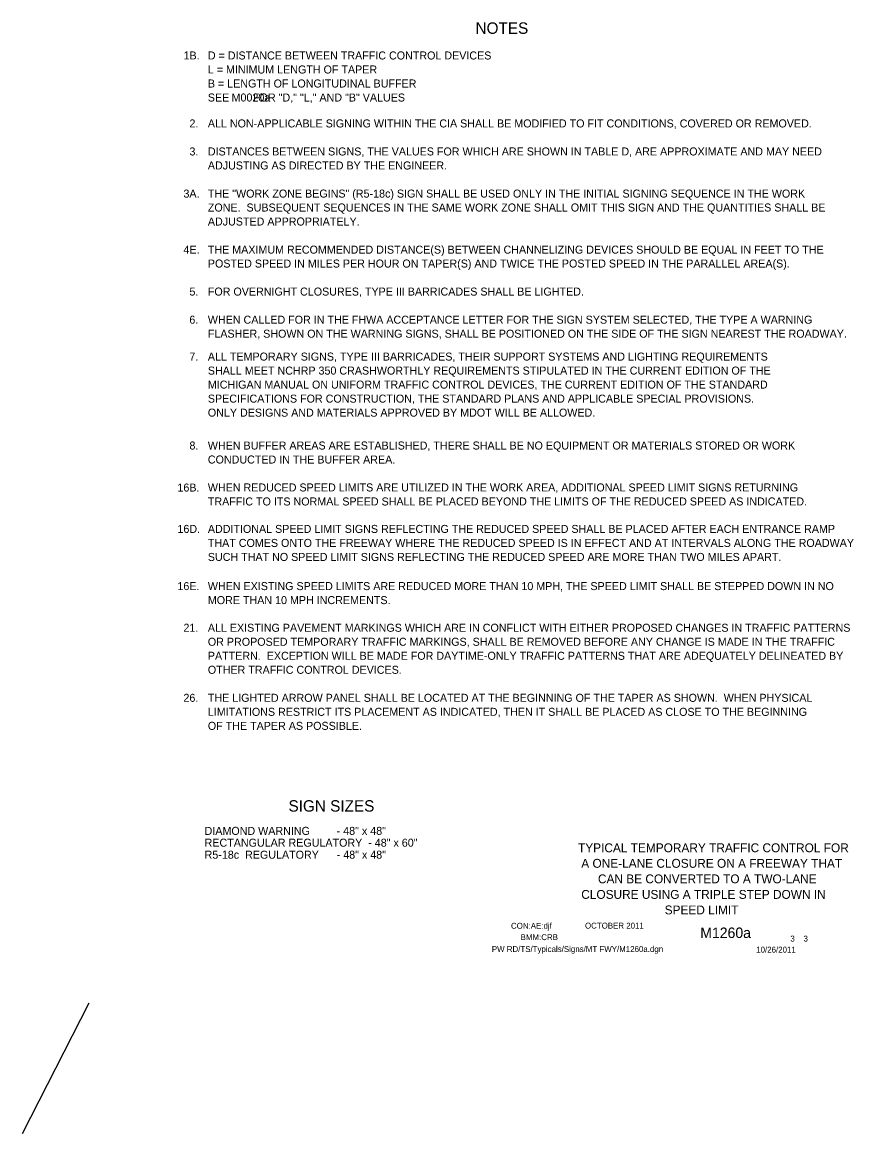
# Model space of a CAD drawing. Extents: x 16503 to 19508, y 5728 to 6974.
# Drawn here: x 18636 to 19508, y 5743 to 6909 of the extents above; entities that cross this region are included whole.
import ezdxf

# ---------------------------------------------------------------- set-up
doc = ezdxf.new("R2010")
doc.units = 0
for name, color, linetype in [('BORDER', 7, 'Continuous'), ('BORDER_SIGNAL_WO', 7, 'Continuous'), ('TYPICAL_TEXT_DIMEN_PR', 7, 'Continuous')]:
    doc.layers.add(name, color=color, linetype=linetype)

msp = doc.modelspace()

# ---------------------------------------------------------------- linework, layer by layer
at = {"layer": 'TYPICAL_TEXT_DIMEN_PR'}
msp.add_line((18705.8, 5880), (18636, 5743), dxfattribs=at)

# ---------------------------------------------------------------- texts
at = {"layer": 'BORDER'}
for s, p in [('TYPICAL TEMPORARY TRAFFIC CONTROL FOR', (19219, 6038.4)), ('A ONE-LANE CLOSURE ON A FREEWAY THAT', (19222.4, 6022.1)), ('CAN BE CONVERTED TO A TWO-LANE ', (19239.9, 6005.8)), ('CLOSURE USING A TRIPLE STEP DOWN IN ', (19222.4, 5989.5)), ('SPEED LIMIT', (19309.9, 5973.2))]:
    msp.add_text(s, height=9.3, dxfattribs=at).set_placement(p)
at = {"layer": 'BORDER_SIGNAL_WO'}
for s, height, p in [('CON:AE:djf  ', 6.2, (19148.7, 5958.1)), ('    OCTOBER 2011    ', 6.2, (19217.1, 5958.3)), ('    M1260a   ', 11, (19330.9, 5948.4)), ('BMM:CRB   ', 6.2, (19158.8, 5946.2)), (' 3    3 ', 6.2, (19439.4, 5944.7)), ('PW RD/TS/Typicals/Signs/MT FWY/M1260a.dgn      ', 6.2, (19128.6, 5933.7)), ('10/26/2011    ', 6.2, (19405.9, 5933.1))]:
    msp.add_text(s, height=height, dxfattribs=at).set_placement(p)
at = {"layer": 'TYPICAL_TEXT_DIMEN_PR'}
for s, height, p in [('NOTES', 12, (19111.5, 6897)), ('1B.', 8.4, (18805.2, 6870.1)), ('D = DISTANCE BETWEEN TRAFFIC CONTROL DEVICES', 8.4, (18830.7, 6870.1)), ('L = MINIMUM LENGTH OF TAPER', 8.4, (18830.7, 6855.4)), ('B = LENGTH OF LONGITUDINAL BUFFER', 8.4, (18830.7, 6840.7)), ('SEE        FOR "D," "L," AND "B" VALUES', 8.4, (18830.7, 6826)), ('M0020a', 8.4, (18855.6, 6826)), ('2.', 8.4, (18811.4, 6798.8)), ('ALL NON-APPLICABLE SIGNING WITHIN THE CIA SHALL BE MODIFIED TO FIT CONDITIONS, COVERED OR REMOVED.', 8.4, (18830.7, 6798.8)), ('3.', 8.4, (18811.4, 6769.4)), ('DISTANCES BETWEEN SIGNS, THE VALUES FOR WHICH ARE SHOWN IN TABLE D, ARE APPROXIMATE AND MAY NEED', 8.4, (18830.7, 6769.4)), ('ADJUSTING AS DIRECTED BY THE ENGINEER.', 8.4, (18830.7, 6754.7)), ('3A.', 8.4, (18805.1, 6725.2)), ('THE "WORK ZONE BEGINS" (R5-18c) SIGN SHALL BE USED ONLY IN THE INITIAL SIGNING SEQUENCE IN THE WORK', 8.4, (18830.7, 6725.2)), ('ZONE.  SUBSEQUENT SEQUENCES IN THE SAME WORK ZONE SHALL OMIT THIS SIGN AND THE QUANTITIES SHALL BE', 8.4, (18830.7, 6710.6)), ('ADJUSTED APPROPRIATELY.', 8.4, (18830.7, 6695.9)), ('4E.', 8.4, (18805.1, 6666.4)), ('THE MAXIMUM RECOMMENDED DISTANCE(S) BETWEEN CHANNELIZING DEVICES SHOULD BE EQUAL IN FEET TO THE', 8.4, (18830.7, 6666.4)), ('POSTED SPEED IN MILES PER HOUR ON TAPER(S) AND TWICE THE POSTED SPEED IN THE PARALLEL AREA(S).', 8.4, (18830.7, 6651.8)), ('5.', 8.4, (18811.4, 6622.4)), ('FOR OVERNIGHT CLOSURES, TYPE III BARRICADES SHALL BE LIGHTED.', 8.4, (18830.7, 6622.4)), ('6.', 8.4, (18811.3, 6592.9)), ('WHEN CALLED FOR IN THE FHWA ACCEPTANCE LETTER FOR THE SIGN SYSTEM SELECTED, THE TYPE A WARNING ', 8.4, (18830.7, 6592.9)), ('FLASHER, SHOWN ON THE WARNING SIGNS, SHALL BE POSITIONED ON THE SIDE OF THE SIGN NEAREST THE ROADWAY.', 8.4, (18830.7, 6578.2)), ('7.', 8.4, (18811.3, 6554.2)), ('ALL TEMPORARY SIGNS, TYPE III BARRICADES, THEIR SUPPORT SYSTEMS AND LIGHTING REQUIREMENTS', 8.4, (18830.7, 6554.2)), ('SHALL MEET NCHRP 350 CRASHWORTHLY REQUIREMENTS STIPULATED IN THE CURRENT EDITION OF THE', 8.4, (18830.7, 6539.5)), ('MICHIGAN MANUAL ON UNIFORM TRAFFIC CONTROL DEVICES, THE CURRENT EDITION OF THE STANDARD', 8.4, (18830.7, 6524.8)), ('SPECIFICATIONS FOR CONSTRUCTION, THE STANDARD PLANS AND APPLICABLE SPECIAL PROVISIONS.', 8.4, (18830.7, 6510.1)), ('ONLY DESIGNS AND MATERIALS APPROVED BY MDOT WILL BE ALLOWED.', 8.4, (18830.7, 6495.4)), ('8.', 8.4, (18811.4, 6460.9)), ('WHEN BUFFER AREAS ARE ESTABLISHED, THERE SHALL BE NO EQUIPMENT OR MATERIALS STORED OR WORK     ', 8.4, (18830.7, 6460.9)), ('CONDUCTED IN THE BUFFER AREA.', 8.4, (18830.7, 6446.2)), ('16B.', 8.4, (18798.8, 6416.8)), ('WHEN REDUCED SPEED LIMITS ARE UTILIZED IN THE WORK AREA, ADDITIONAL SPEED LIMIT SIGNS RETURNING', 8.4, (18830.7, 6416.9)), ('TRAFFIC TO ITS NORMAL SPEED SHALL BE PLACED BEYOND THE LIMITS OF THE REDUCED SPEED AS INDICATED.', 8.4, (18830.7, 6402.2)), ('16D.', 8.4, (18798.8, 6373.4)), ('ADDITIONAL SPEED LIMIT SIGNS REFLECTING THE REDUCED SPEED SHALL BE PLACED AFTER EACH ENTRANCE RAMP', 8.4, (18830.7, 6373.4)), ('THAT COMES ONTO THE FREEWAY WHERE THE REDUCED SPEED IS IN EFFECT AND AT INTERVALS ALONG THE ROADWAY', 8.4, (18830.7, 6358.7)), ('SUCH THAT NO SPEED LIMIT SIGNS REFLECTING THE REDUCED SPEED ARE MORE THAN TWO MILES APART.', 8.4, (18830.7, 6344)), ('16E.', 8.4, (18798.8, 6313.4)), ('WHEN EXISTING SPEED LIMITS ARE REDUCED MORE THAN 10 MPH, THE SPEED LIMIT SHALL BE STEPPED DOWN IN NO', 8.4, (18830.7, 6313.4)), ('MORE THAN 10 MPH INCREMENTS.', 8.4, (18830.7, 6298.7)), ('21.', 8.4, (18805.1, 6269.7)), ('ALL EXISTING PAVEMENT MARKINGS WHICH ARE IN CONFLICT WITH EITHER PROPOSED CHANGES IN TRAFFIC PATTERNS', 8.4, (18830.7, 6269.7)), ('OR PROPOSED TEMPORARY TRAFFIC MARKINGS, SHALL BE REMOVED BEFORE ANY CHANGE IS MADE IN THE TRAFFIC', 8.4, (18830.7, 6255)), ('PATTERN.  EXCEPTION WILL BE MADE FOR DAYTIME-ONLY TRAFFIC PATTERNS THAT ARE ADEQUATELY DELINEATED BY', 8.4, (18830.7, 6240.3)), ('OTHER TRAFFIC CONTROL DEVICES.', 8.4, (18830.7, 6225.6)), ('26.', 8.4, (18805.1, 6196.2)), ('THE LIGHTED ARROW PANEL SHALL BE LOCATED AT THE BEGINNING OF THE TAPER AS SHOWN.  WHEN PHYSICAL', 8.4, (18830.7, 6196.2)), ('LIMITATIONS RESTRICT ITS PLACEMENT AS INDICATED, THEN IT SHALL BE PLACED AS CLOSE TO THE BEGINNING', 8.4, (18830.7, 6181.5)), ('OF THE TAPER AS POSSIBLE.', 8.4, (18830.7, 6166.8)), ('SIGN SIZES', 12, (18915.3, 6081)), ('DIAMOND WARNING         - 48" x 48"', 8.4, (18827.3, 6056.6)), ('RECTANGULAR REGULATORY  - 48" x 60"', 8.4, (18827.3, 6044.2)), ('R5-18c  REGULATORY      - 48" x 48"', 8.4, (18827.3, 6031.6))]:
    msp.add_text(s, height=height, dxfattribs=at).set_placement(p)

doc.saveas('drawing.dxf')
